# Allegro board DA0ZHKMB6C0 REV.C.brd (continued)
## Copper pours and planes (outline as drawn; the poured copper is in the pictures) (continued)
VDD10 on BOTTOM (solid shape): 150.84,70.38 150.84,68.81 148.6,66.57 146.93,66.57 146.91,66.57 146.65,66.47 146.55,66.21 146.55,66.19 145.66,65.3 145.28,65.3 145.05,65.53 145.05,65.53 144.64,65.94 144.49,65.94 143.86,66.57 143.64,66.57 143.63,66.58 143.12,66.58 143.11,66.57 142.84,66.57 142.21,65.94 142.21,60.6 142.08,60.48 141.06,60.48 140.94,60.6 140.94,67.21 142.08,68.35 143.58,68.35 143.68,68.25 143.68,68.25 143.72,68.22 144.05,68.22 144.26,68 144.26,67.71 144.33,67.21 144.83,67.27 145.08,67.27 145.13,67.23 145.2,67.21 145.21,67.21 145.22,67.19 145.53,67.19 145.54,67.2 145.56,67.21 145.68,67.27 145.73,67.4 145.74,67.41 145.74,67.7 145.73,67.72 145.67,67.83 145.56,67.89 145.54,67.89 145.53,67.9 145.52,67.9 145.24,68.18 145.22,68.29 145.32,68.35 147.01,68.35 147.07,68.34 147.11,68.29 147.11,68.1 147.17,68.03 147.22,67.97 147.28,67.93 147.34,67.86 147.61,67.86 147.69,67.94 147.72,67.97 147.75,68.01 147.81,68.06 147.88,68.07 147.94,68.02 148.51,67.95 148.41,68.52 148.36,68.59 148.39,68.68 148.57,68.86 148.57,69.76 149.32,70.51 150.71,70.51
VDD10 on IN2 (solid shape): outline of 94 points within 149.04,62.64 151.73,70.38
VDDREG/VDD33 on TOP (solid shape): 149.88,65.35 149.88,63.99 149.46,63.95 149.33,63.55 149.31,63.46 149.23,63.42 147.62,63.42 147.57,63.47 147.57,63.55 147.62,63.6 148.63,63.6 148.84,63.81 148.84,64.74 149.5,65.41 149.83,65.41
VDDREG/VDD33 on BOTTOM (solid shape): 150.59,67.34 150.59,64.54 150.46,64.41 149.85,64.41 149.72,64.29 149.44,64.29 148.78,64.95 147.51,64.95 147.41,65.05 147.41,66.1 147.52,66.21 148.78,66.21 150.08,67.51 150.41,67.51
554EN_1.0V on TOP (solid shape): 33.11,54.38 33.11,53.59 33.04,53.52 32.4,53.52 32.12,53.24 31.37,53.24 31.3,53.31 31.3,53.88 31.4,53.98 31.75,53.98 32.26,54.48 32.32,54.49 33,54.49
554EN_1.0V on BOTTOM (solid shape): 31.59,53.81 31.65,53.75 32.22,53.75 32.28,53.69 32.28,53.36 32.15,53.23 31.22,53.23 30.95,53.49 30.95,54.25 31.08,54.38 31.59,54.38
554LX_1.0V on TOP (solid shape): 27.93,53.98 27.93,53.96 28.24,53.8 28.54,53.96 28.55,53.98 28.59,54 29.6,54 29.6,53.41 29.8,53.41 29.8,54 30.11,54 30.11,53.43 30.3,53.43 30.3,54 30.57,54 30.6,53.97 30.6,53.37 30.56,53.36 30.25,52.94 30.64,52.6 30.96,52.6 31.08,52.48 31.08,51.33 31.84,50.57 31.84,45.24 31.72,45.11 29.24,45.11 29.16,45.14 29.14,45.22 29.04,45.51 28.76,45.62 28.54,45.52 28.43,45.31 28.43,45.29 28.41,45.27 28.35,45.27 28.29,45.33 28.29,46.69 27.78,47.19 27.35,47.19 26.76,47.78 26.76,53.52 27.25,54 27.88,54
554LX_1.8V on TOP (solid shape): 111.34,52.93 112.5,52.93 112.5,52.36 112.7,52.36 112.7,52.93 113,52.93 113,52.35 113.2,52.35 113.2,52.93 113.43,52.93 113.5,52.86 113.5,52.22 114.52,51.21 114.52,45.87 111.89,43.24 110.64,43.24 110.46,43.43 110.46,52.98 110.58,53.11 111.17,53.11
8690AGND on TOP (solid shape): 138.14,20.85 138.14,18.95 138.27,18.82 138.27,17.61 138.21,17.55 138.14,17.55 138.08,17.61 138.08,18.7 137.89,18.9 136.62,18.9 136.59,18.92 136.59,20.63 136.42,20.8 135.35,20.8 135.27,20.87 135.27,20.93 135.32,20.98 138.01,20.98
8690AGND on BOTTOM (solid shape): outline of 283 points within 132.93,13.87 140.94,22.5
51216DRVH on TOP (solid shape): 32.73,33.45 32.93,33.25 33.32,33.25 33.47,33.1 33.47,32.72 33.32,32.56 33.04,32.56 33.02,32.55 32.53,33.05 32.53,34.26 32.73,34.26
51216DRVH on TOP (solid shape): 36.61,27.31 36.61,26.9 36.92,26.59 36.92,25.99 36.86,25.93 35.75,25.93 35.65,26.02 35.65,27.33 35.78,27.46 36.46,27.46
51216DRVL on TOP (solid shape): 29.56,30.05 29.56,29.41 29.46,29.31 28.29,29.31 28.19,29.42 28.19,29.98 28.31,30.1 29.51,30.1
51216SW on TOP (solid shape): 32.33,33.05 33.06,32.31 33.24,32.31 33.27,32.28 33.27,31.8 33.24,31.78 32.58,31.78 32.12,32.23 32.12,34.26 32.33,34.26
51216SW on TOP (solid shape): 32.68,28.45 32.68,28.02 33.54,27.16 35.32,27.16 35.44,27.03 35.44,23.54 35.22,23.32 31.72,23.32 31.7,23.33 30.56,23.33 30.56,23.33 28.65,23.33 28.54,23.44 28.54,28.55 28.76,28.77 32.36,28.77
95833_LGATEG on BOTTOM (solid shape): 125.16,66.42 126.13,66.42 126.15,66.4 126.15,66.27 126.13,66.24 125.11,66.24 124.78,65.91 124.58,65.91 124.5,65.99 124.5,66.5 124.58,66.57 125.01,66.57
95833_PHASE1 on TOP (solid shape): 113.71,72.97 113.71,72.21 114.16,71.76 118.28,71.76 118.28,69.6 110.83,69.6 110.76,69.66 110.76,71.07 110.84,71.15 112.03,71.15 112.09,71.22 112.09,71.63 112.02,71.71 110.84,71.71 110.76,71.79 110.76,73.44 110.85,73.53 113.15,73.53
95833_PHASE1 on BOTTOM (solid shape): 126.13,64.39 126.13,64.26 126.1,64.24 125.31,64.24 125.06,63.98 124.63,63.98 123.94,63.3 123.13,63.3 123.1,63.32 123.1,64.03 123.33,64.26 124.04,64.26 124.06,64.27 124.29,64.27 124.43,64.41 124.5,64.41 124.63,64.29 124.96,64.29 125.1,64.43 126.08,64.43
95833_PHASEG on TOP (solid shape): 113.71,79.96 118.12,79.96 118.3,79.77 118.3,77.96 118.15,77.81 114.37,77.81 113.36,76.79 110.91,76.79 110.76,76.94 110.76,78.2 110.82,78.26 112.07,78.26 112.12,78.31 112.12,78.74 112.04,78.82 110.82,78.82 110.76,78.88 110.76,80.28 110.92,80.44 113.22,80.44
95833_PHASEG on BOTTOM (solid shape): 125.26,66.93 126.03,66.93 126.13,66.83 126.13,66.68 126.1,66.65 125.21,66.65 125.04,66.83 124.42,66.83 124.17,66.57 123.02,66.57 122.98,66.61 122.98,67.56 123,67.59 124.6,67.59
95833_UGATE1 on TOP (solid shape): 114.34,67.64 114.64,67.64 114.72,67.55 114.72,67.09 114.63,67.01 113.75,67.01 113.12,67.63 113.12,67.84 113.38,68.1 113.88,68.1
95833_UGATE1 on BOTTOM (solid shape): 126.1,63.98 126.1,63.63 126.05,63.58 125.92,63.58 125.56,63.21 125.12,63.21 125.11,63.2 124.71,63.2 124.63,63.27 124.63,63.63 124.78,63.78 125.16,63.78 125.39,64.01 126.08,64.01
+BATCHG on TOP (solid shape): outline of 3063 points within 59.27,2.87 119.85,27.05
+BATCHG on BOTTOM (solid shape): 63.8,15.9 63.88,15.86 63.94,15.44 64.23,15.29 64.85,15.29 64.99,15.29 65.14,15.35 65.2,15.5 65.21,15.65 65.23,15.87 65.3,15.9 65.88,15.9 65.94,15.84 65.94,15.74 65.93,15.65 65.94,15.55 65.94,12.44 65.9,12.36 65.8,12.35 65.32,12.01 65.8,11.68 65.9,11.67 65.94,11.59 65.94,10.79 65.59,10.44 61.64,10.44 61.33,10.74 61.33,14.76 61.71,15.14 62.04,15.14 62.22,15.09 62.41,15.14 62.98,15.14 63.21,15.37 63.21,15.75 63.36,15.9
+LCDVCC on TOP (solid shape): 31.52,67.96 31.52,64.82 31.37,64.67 28.03,64.67 27.91,64.8 27.91,67.93 28.08,68.1 31.38,68.1
+LCDVCC on BOTTOM (solid shape): 28.86,62.36 28.86,62.12 28.63,61.9 28.63,61.3 28.51,61.17 27.42,61.17 27.29,61.31 27.29,62.35 27.47,62.54 28.68,62.54
+LCDVCC on BOTTOM (solid shape): 31.73,67.87 31.73,66.39 31.74,66.38 31.95,66.38 31.96,66.39 31.96,67.88 32,67.92 32.19,67.92 32.24,67.87 32.24,66.39 32.24,66.38 32.45,66.38 32.46,66.39 32.46,67.87 32.51,67.92 32.68,67.92 32.73,67.87 32.73,65.42 32.61,65.3 32.61,64.88 32.51,64.77 30.35,64.77 29.68,65.44 29.68,66.07 29.81,66.19 31.33,66.19 31.46,66.32 31.46,67.87 31.51,67.92 31.68,67.92
+LCDVCC on IN1 (solid shape): 31.55,65.88 31.55,65.21 30.04,63.7 30.04,61.98 29.9,61.84 29.49,61.84 29.47,61.87 29.44,61.91 29.4,61.95 29.36,61.98 29.31,62 29.26,62.02 29.2,62.03 29.15,62.03 29.1,62.02 29.04,62 28.99,61.98 28.95,61.95 28.91,61.91 28.88,61.87 28.86,61.84 27.48,61.84 27.33,61.99 27.33,63.53 28.69,63.53 28.69,63.5 28.7,63.45 28.72,63.4 28.74,63.35 28.77,63.3 28.81,63.26 28.85,63.23 28.89,63.2 28.94,63.18 29,63.17 29.05,63.17 29.1,63.17 29.15,63.18 29.2,63.2 29.25,63.23 29.29,63.26 29.33,63.3 29.36,63.35 29.38,63.4 29.4,63.45 29.4,63.5 29.4,63.55 29.4,63.61 29.38,63.66 29.36,63.7 29.33,63.75 29.29,63.79 29.25,63.82 29.2,63.85 29.15,63.87 29.1,63.88 29.05,63.88 29,63.88 28.94,63.87 28.89,63.85 28.85,63.82 28.81,63.79 28.77,63.75 28.74,63.7 28.72,63.66 28.7,63.61 28.69,63.55 28.69,63.53 27.33,63.53 27.33,64.3 29.18,66.15 31.28,66.15
+TPVDD on BOTTOM (solid shape): 58.53,17.83 58.53,16.71 58.17,16.35 57.6,16.35 57.24,16.71 57.24,17.81 57.34,17.91 58.44,17.91
+TPVDD_1 on BOTTOM (solid shape): 59.74,20.51 59.74,19.06 59.63,18.95 59.02,18.95 58.82,19.15 58.82,20.6 58.4,21.02 57.08,21.02 56.66,20.6 56.66,16.46 56.35,16.15 56.35,15.37 56,15.01 51.52,15.01 51.4,15.13 51.4,16.41 51.53,16.54 52.92,16.54 53.97,17.58 54,17.58 54.08,17.54 54.1,17.46 54.53,17.07 54.77,17.59 54.76,17.61 54.77,17.64 54.86,17.73 54.86,19.28 54.17,19.96 52.34,19.96 52.24,20.07 52.24,20.85 52.32,20.93 55.57,20.93 56.46,21.82 58.44,21.82
+VA on TOP (solid shape): 154.33,88.19 154.33,82.68 154.23,82.58 150.8,82.58 150.67,82.7 150.67,88.18 150.91,88.42 154.1,88.42
+VA on BOTTOM (solid shape): 153.34,85.62 153.34,82.83 153.09,82.58 152.2,82.58 151.82,82.19 151.82,81.81 151.56,81.56 150.8,81.56 150.67,81.69 150.67,85.37 151.18,85.88 153.09,85.88
+VA_IACM on TOP (solid shape): 147.67,22.5 157.16,22.5 157.2,22.47 157.2,22.41 157.18,22.4 156.99,22.07 157.15,21.72 157.19,21.64 157.15,21.56 157.01,21.12 157.37,20.83 157.41,20.81 157.42,20.78 157.42,19.13 157.17,18.87 155.52,18.87 154.91,18.26 154.91,14.23 154.75,14.07 148.43,14.07 148.3,14.2 148.3,15.01 146.9,16.41 146.9,20.6 145.38,22.12 143.14,22.12 143.09,22.17 143.09,23.39 143.22,23.52 146.65,23.52
+VA_IACM on BOTTOM (solid shape): 156.33,85.76 156.33,84.01 157.15,83.2 157.15,82.07 156.9,81.81 155.23,81.81 154.74,82.31 154.35,82.31 154.1,82.55 154.1,85.6 154.48,85.98 156.11,85.98
+VA_IACM on SVCC (solid shape): outline of 85 points within 142.21,12.7 157.14,84.99
+VAD on TOP (solid shape): 142.43,19.69 142.64,19.69 142.66,19.71 145.58,19.71 145.81,19.47 145.81,14.22 145.69,14.1 145.05,14.1 144.9,14.25 144.9,14.73 144.54,15.09 143.02,15.09 142.59,15.52 142.59,16.3 140.48,18.4 140.48,18.95 140.49,18.99 140.53,19 141.48,19 141.48,19.2 140.53,19.2 140.49,19.21 140.48,19.25 140.48,19.35 140.49,19.38 140.53,19.4 141.48,19.4 141.48,19.6 140.53,19.6 140.49,19.61 140.48,19.65 140.48,19.75 140.49,19.79 140.53,19.8 141.48,19.8 141.48,20 140.53,20 140.49,20.01 140.48,20.05 140.48,20.15 140.49,20.18 140.53,20.2 141.48,20.2 141.48,20.4 140.53,20.4 140.49,20.41 140.48,20.45 140.48,20.55 140.49,20.58 140.53,20.6 141.52,20.6
ADOGND on TOP (solid shape): 22.02,83.69 22.02,82.94 22.32,82.65 22.32,81.04 22.23,80.96 21.05,80.96 21.02,80.99 21.02,81.22 21.1,81.29 21.46,81.29 21.8,81.63 21.8,82.38 21.7,82.48 21.7,82.96 21.29,83.37 21.29,83.64 21.49,83.84 21.87,83.84
ADOGND on TOP (solid shape): 21.81,85.53 21.81,84.63 21.66,84.47 19.4,84.47 19.4,84.48 13.28,84.48 13.23,84.51 13.23,84.53 13.01,84.83 12.66,84.95 11.94,84.95 11.63,84.86 11.41,84.62 11.41,84.61 11.15,84.35 5.96,84.35 5.4,84.91 2.96,84.91 2.87,84.88 2.78,84.84 2.56,84.67 2.47,84.4 2.47,82.59 2.44,82.54 2.42,82.54 1.63,81.49 2.43,80.46 2.45,80.46 2.47,80.43 2.47,79.73 3.28,78.92 3.3,78.8 3.2,78.75 3.16,78.75 2.44,78.75 1.85,78.15 2.44,77.55 3.16,77.55 3.64,77.8 3.72,78.34 3.71,78.37 3.77,78.43 3.8,78.4 4.05,78.4 4.25,78.25 4.49,78.2 5.21,78.2 5.45,78.25 5.65,78.4 8.09,78.4 8.65,77.84 8.65,75.01 8.65,73.61 9.31,72.95 9.31,66.25 10.39,65.16 13.55,65.16 13.62,65.08 13.62,64.81 12,63.19 3.26,63.19 2.2,66 0.61,68.55 0.53,68.69 0.51,68.84 0.51,75.8 0.57,76.04 1.27,76.76 1.46,77.5 1.46,78.45 1.46,84.4 1.46,84.42 1.46,85.12 14.92,85.12 15.29,85.49 20.6,85.49 21.02,85.53 21.44,85.64 21.71,85.64
ADOGND on BOTTOM (solid shape): outline of 93 points within 0.51,63.19 21.81,85.64
ADOGND on SGND (solid shape): outline of 306 points within 0.51,63.2 33.42,85.63
ADOGND on IN1 (solid shape): 21.81,85.53 21.81,84.63 21.66,84.47 19.4,84.47 19.4,84.48 13.28,84.48 13.23,84.51 13.23,84.53 13.01,84.83 12.66,84.95 11.94,84.95 11.67,84.88 11.46,84.7 11.43,84.66 11.41,84.61 11.15,84.35 5.96,84.35 5.4,84.91 2.96,84.91 2.87,84.88 2.78,84.84 2.56,84.67 2.47,84.4 2.47,82.59 2.44,82.54 2.42,82.54 1.63,81.49 2.43,80.46 2.47,80.43 2.47,78.75 2.43,78.75 1.98,78.53 1.85,78.05 1.87,77.99 1.89,77.93 1.94,77.83 2.01,77.74 2.01,77.43 3.37,76.07 8.09,76.07 9.64,74.52 9.64,73.37 9.31,73.03 9.31,66.25 10.39,65.16 13.55,65.16 13.62,65.08 13.62,64.81 12,63.19 3.26,63.19 2.2,66 0.61,68.55 0.53,68.69 0.51,68.84 0.51,75.8 0.57,76.04 1.27,76.76 1.46,77.5 1.46,78.45 1.46,84.4 1.46,84.42 1.46,85.27 1.46,85.38 1.48,85.5 13.01,85.5 13.11,85.49 13.2,85.49 20.6,85.49 21.02,85.53 21.44,85.64 21.71,85.64
ADOGND on IN2 (solid shape): outline of 81 points within 0.51,63.19 21.81,85.64
ADOGND on SVCC (solid shape): outline of 294 points within 0.76,63.2 33.42,85.5
CHG_LX on TOP (solid shape): 131.66,25.28 131.66,23.33 132.11,22.89 133.19,22.89 134.28,21.79 136.52,21.79 136.59,21.87 136.59,22.45 136.6,22.48 136.61,22.5 136.64,22.5 137.61,22.5 137.68,22.58 137.68,23.75 137.69,23.78 137.71,23.79 137.86,23.79 137.88,23.78 137.89,23.75 137.89,22.8 137.89,22.8 137.89,22.58 137.96,22.5 138.14,22.5 138.16,22.48 138.17,22.45 138.17,21.39 138.16,21.36 138.14,21.34 138.12,21.34 136.41,21.34 136.29,21.21 135.12,21.21 134.36,20.45 132.48,20.45 132.08,20.05 132.08,18.3 131.72,17.93 127.73,17.93 127.47,18.19 127.47,21.4 136.28,21.4 136.28,21.6 135.29,21.6 135.29,21.4 127.47,21.4 127.47,24.13 127.75,24.41 129.63,24.41 129.76,24.54 129.76,25.3 130.01,25.55 131.39,25.55
CHG_VBATT on TOP (solid shape): 142.18,24 142.37,24 142.42,23.98 142.47,23.98 142.69,23.76 142.69,23.75 142.71,23.73 142.71,22.25 142.26,21.79 142.26,21.06 142,20.8 140.48,20.8 140.48,21 141.48,21 141.48,21.2 140.48,21.2 140.48,21.4 141.48,21.4 141.48,21.6 140.48,21.6 140.48,21.8 141.48,21.8 141.48,22 140.48,22 140.48,22.2 141.48,22.2 141.48,22.4 140.48,22.4 140.48,23.72 140.78,24.03 142.15,24.03
CHG_VBATT on TOP (solid shape): 126.58,28.14 126.58,18.44 126.2,18.06 121.93,18.06 121.56,18.44 121.56,20.56 121.57,20.59 121.59,20.61 121.89,20.98 121.59,21.35 121.57,21.37 121.56,21.4 121.56,22.83 120.74,23.65 120.74,26.82 120.97,27.05 124.36,27.05 125.54,28.23 126.5,28.23
CHG_VBATT on IN1 (solid shape): outline of 348 points within 123.03,22.38 143.68,26.92
CODEC_VREF on TOP (solid shape): 17.26,75.84 18.14,75.84 18.23,75.76 18.34,75.76 18.43,75.67 19.47,75.67 19.47,75.67 19.47,75.49 19.46,75.48 18.44,75.48 18.43,75.46 17.09,75.46 16.91,75.29 16.55,75.29 16.45,75.39 16.45,75.82 16.53,75.9 17.21,75.9
CORE_V1P05_S3_PW on TOP (solid shape): 70.74,57.96 71,58.09 71.16,58.09 72.05,57.2 72.26,57.2 72.3,57.2 72.43,57.2 72.93,57.71 73.09,57.71 73.47,57.46 73.85,57.71 73.95,57.71 74.08,57.58 74.08,56.69 73.95,56.57 73.77,56.57 73.73,56.58 73.61,56.67 73.45,56.7 73.43,56.71 73.39,56.75 73.37,56.8 73.33,56.84 73.28,56.9 73.25,56.92 73.17,57 72.89,57 72.83,56.94 72.49,56.94 72.3,57 72.12,56.94 72.03,56.94 71.92,56.82 71.79,56.82 70.9,57.71 70.85,57.71 70.84,57.71 70.74,57.73 70.64,57.71 70.63,57.71 70.06,57.71 70.05,57.71 69.83,57.7 69.69,57.53 69.69,57.51 69.38,57.2 69.12,57.2 68.97,57.05 68.96,57.05 68.47,56.57 68.24,56.57 68.17,56.64 68.15,56.67 68.13,56.7 68.13,57.61 68.29,57.76 69.3,57.76 69.54,58 69.81,58 69.82,57.99 70.01,57.96 70.17,58.07 70.21,58.09 70.48,58.09
CORE_V1P05_S3_PW on BOTTOM (solid shape): 60.9,54.61 60.9,53.62 60.7,53.42 60.29,53.42 60.14,53.57 60.14,53.95 60.01,54.08 60.01,54.64 60.06,54.69 60.82,54.69
CORE_V1P05_S3_PW on BOTTOM (solid shape): 71.52,57.71 71.57,57.71 71.59,57.7 71.6,57.68 71.91,57.49 72.23,57.68 72.24,57.7 72.26,57.71 73.06,57.71 73.44,57.33 73.54,57.33 73.7,57.18 73.7,56.97 73.54,56.82 70.77,56.82 70.7,56.85 70.67,56.91 70.34,57.5 70.02,56.91 69.99,56.85 69.92,56.82 68.57,56.82 68.49,56.74 67.96,56.74 67.86,56.85 67.86,57.23 67.96,57.33 68.6,57.33 68.6,57.33 69.51,57.33 69.51,57.33 69.59,57.33 69.97,57.71 70.1,57.71 70.25,57.86 71.37,57.86
CORE_V1P05_S3_PW on IN1 (solid shape): 71.56,58.04 71.58,58.02 71.57,57.99 71.73,57.57 72.18,57.64 72.19,57.65 72.21,57.66 73.15,57.66 73.17,57.65 73.19,57.64 73.43,57.51 73.69,57.58 73.72,57.59 73.76,57.58 73.88,57.46 73.88,56.77 73.75,56.64 73.59,56.64 73.53,56.66 73.46,56.67 72.87,56.67 72.85,56.64 72.02,56.64 72.01,56.64 71.91,56.66 71.81,56.64 71.81,56.64 71.14,56.64 71.1,56.68 71.09,56.67 70.69,56.67 70.6,56.73 70.61,56.84 70.35,57.43 70.08,56.84 70.1,56.73 70.01,56.67 69.69,56.67 69.59,56.57 69.01,56.57 68.78,56.66 68.55,56.58 68.54,56.57 68.42,56.57 68.34,56.64 68.34,58.15 68.44,58.24 71.37,58.24
CORE_V1P05_S3_PW on IN2 (solid shape): outline of 205 points within 60.25,53.26 69.36,57.54
DARM_V1P0_SOIX_PWR on TOP (solid shape): 66.89,56.93 67.01,56.79 67.16,56.73 67.18,56.73 67.47,56.44 68.49,56.44 68.57,56.52 68.78,56.73 68.8,56.73 68.97,56.79 69.1,56.93 69.12,56.95 69.97,56.95 70.25,56.67 70.42,56.67 70.49,56.6 70.5,56.59 70.55,56.52 70.62,56.47 70.65,56.44 71.79,56.44 72.11,56.76 72.18,56.82 72.2,56.82 72.43,56.82 72.55,56.69 72.55,55.93 72.43,55.81 71.54,55.81 71.16,56.19 70.86,56.19 70.85,56.19 70.66,56.21 70.51,56.08 70.5,56.07 70.48,56.06 70.27,56.06 70.14,56.19 70.08,56.19 70.07,56.19 69.83,56.19 69.69,56 69.69,55.99 69.38,55.68 69.12,55.68 68.62,56.19 68.51,56.19 68.5,56.19 68.38,56.22 68.27,56.19 68.26,56.19 68.24,56.19 67.85,55.81 66.71,55.81 66.58,55.93 66.58,56.82 66.71,56.95 66.86,56.95
DARM_V1P0_SOIX_PWR on BOTTOM (solid shape): outline of 416 points within 48.1,53.35 72.17,57.08
DDI_V1P0_SOIX on BOTTOM (solid shape): 49.19,57 49.19,56.85 49.29,56.74 51.78,56.74 51.88,56.64 51.88,55.96 51.83,55.9 51.29,55.9 50.82,56.06 50.64,55.59 50.64,55.49 50.55,55.45 50.4,55.3 48.94,55.3 48.76,55.47 48.17,55.47 48.12,55.52 48.12,56.08 48.66,56.62 48.66,57.05 48.76,57.15 49.04,57.15
DDI_V1P0_SOIX on IN2 (solid shape): 67.6,65.46 67.6,65.37 67.6,63.97 67.6,63.91 67.6,63.86 67.6,63.3 67.52,63.22 67.1,63.22 66.84,63.48 66.84,64.5 66.85,64.51 66.85,64.88 66.84,64.89 66.84,65.08 66.71,65.2 66.38,65.2 66.23,65.35 66.23,65.62 66.33,65.71 67.35,65.71
HWPG1.8VD on BOTTOM (solid shape): 119.09,59.59 119.09,59.21 118.84,58.95 117.95,58.95 117.82,59.08 117.82,60.3 117.84,60.34 117.87,60.35 118.33,60.35
L_SPK+ on TOP (solid shape): 21.91,71.91 21.95,71.89 21.97,71.86 21.97,70.56 21.79,70.38 21.79,69.42 21.78,69.42 21.78,69.04 21.78,68.63 21.71,68.55 21.43,68.55 21.31,68.67 21.31,69.86 21.44,69.99 21.44,70.32 21.76,70.64 21.76,71.91 21.76,71.91
L_SPK+ on IN1 (solid shape): 21.78,69.98 21.78,67.97 21.71,67.89 21.12,67.89 21.03,67.99 21.01,68.01 21.01,68.04 21.02,68.14 21,68.25 21,68.26 21,68.73 21.3,69.04 21.3,69.77 21.35,69.82 21.35,70.03 21.4,70.08 21.68,70.08
L_SPK+_1 on TOP (solid shape): 10.63,9.3 10.63,6.88 10.38,6.63 9.01,6.63 8.86,6.78 8.86,9.3 9.11,9.55 10.38,9.55
L_SPK+_1 on BOTTOM (solid shape): 13.17,12.24 13.17,9.42 12.49,8.74 9.47,8.74 9.26,8.53 9.11,8.53 8.98,8.66 8.98,9.63 9.16,9.8 9.36,9.8 9.62,10.06 11.01,10.06 12.03,11.07 12.03,11.99 12.36,12.32 13.1,12.32
L_SPK- on TOP (solid shape): 22.31,71.91 22.35,71.89 22.37,71.86 22.37,70.61 22.44,70.53 22.44,69.04 22.34,68.94 22.04,68.94 21.94,69.04 21.94,70.38 22.16,70.61 22.16,71.91
L_SPK- on IN1 (solid shape): 22.5,69.98 22.5,69.93 22.49,69.93 22.47,69.8 22.49,69.67 22.5,69.67 22.5,69.32 22.49,69.32 22.54,68.98 22.84,68.83 22.85,68.83 23.16,68.53 23.16,68.25 22.98,68.07 22.4,68.07 21.89,68.59 21.89,69.95 22.01,70.08 22.39,70.08
L_SPK-_1 on TOP (solid shape): 12.67,9.38 12.67,6.76 12.54,6.63 11.4,6.63 11.39,6.64 11.27,6.64 11.14,6.77 11.14,9.3 11.4,9.55 12.49,9.55
L_SPK-_1 on BOTTOM (solid shape): 14.44,12.22 14.44,8.79 13.43,7.77 13.43,6.76 13.17,6.5 12.16,6.5 12.03,6.63 12.03,7.77 13.55,9.3 13.55,12.27 13.58,12.29 14.37,12.29
LAN_MCT0 on TOP (solid shape): 141.07,84.59 141.07,84.32 140.82,84.06 140.82,84 140.82,82.76 140.05,82.76 140.05,84.67 140.07,84.7 140.96,84.7
LAN_MCT1 on TOP (solid shape): 139.54,84.96 139.54,82.78 138.78,82.78 138.78,84.15 138.15,84.78 137.73,84.78 137.65,84.86 137.65,85.29 137.85,85.5 139,85.5
LAN_MCT2 on TOP (solid shape): 133.67,84.77 133.67,84.31 133.43,84.07 133.24,84.07 133.18,84 133.18,82.77 132.42,82.77 132.42,84.04 132.43,84.05 132.43,85.01 132.64,85.22 133.22,85.22
LAN_MCT2 on BOTTOM (solid shape): 134.42,85.05 134.48,85.01 134.55,84.96 134.55,83.08 134.45,82.98 133.09,82.98 133.03,83.04 133.03,85.02 133.08,85.05
LAN_MCT3 on TOP (solid shape): 131.92,84.82 131.92,82.96 131.92,82.77 131.17,82.77 131.17,84.21 130.65,84.73 130.65,85.12 130.78,85.24 131.5,85.24
LANCT3 on TOP (solid shape): 147.29,80.84 147.29,77.99 147.08,77.78 144.92,77.78 144.75,77.95 144.75,80.85 144.82,80.92 147.2,80.92
LANCT3 on BOTTOM (solid shape): 145.46,83.06 145.46,81.52 145.89,81.09 147.21,81.09 147.26,81.04 147.26,80.1 147.14,79.97 139.01,79.97 138.08,80.9 129.81,80.9 129.4,81.32 129.4,82.02 129.6,82.22 138.89,82.22 139.44,81.67 143.07,81.67 143.78,82.38 143.78,83.29 143.88,83.39 145.13,83.39
LANVCC on TOP (solid shape): 144.69,65.23 144.69,64.14 144.67,64.11 144.54,64.11 143.86,64.8 143.86,65.43 143.98,65.56 144.36,65.56
LANVCC on BOTTOM (solid shape): outline of 171 points within 142.43,57.28 149.06,65.74
LANVCC on IN2 (solid shape): 145.53,57.81 146.29,57.81 146.63,57.48 146.63,57.35 146.5,57.23 145.48,57.23 144.21,58.5 144.04,58.5 143.93,58.54 143.81,58.54 143.8,58.54 143.78,58.55 143.58,58.75 143.58,59 143.83,59.26 144.08,59.26
LGND on TOP (solid shape): 147.16,84.75 147.16,82.45 144.87,82.45 144.75,82.58 144.75,85.37 144.87,85.5 146.41,85.5
LGND on BOTTOM (solid shape): outline of 106 points within 124.04,83.64 146.93,101.19
MIC2_MIC_RING2_MIC on TOP (solid shape): 29.94,81.99 32,81.99 32.07,81.92 32.07,80.54 32,80.47 30.6,80.47 29.84,79.71 28.97,79.71 28.87,79.81 28.87,81.91 29.09,82.13 29.8,82.13
MIC2_MIC_RING2_MIC on IN1 (solid shape): outline of 445 points within 3.12,80.8 32.07,84.71
MIC2_MIC_SLEEVE_MIC on TOP (solid shape): 10.1,76.51 10.1,75.13 9.87,74.9 9.06,74.9 8.88,75.08 8.88,76.53 9.03,76.68 9.92,76.68
MIC2_MIC_SLEEVE_MIC on TOP (solid shape): 12.69,74.36 12.69,73.15 12.59,73.05 10.75,73.05 10.54,73.26 10.54,73.42 10.56,73.43 10.56,73.97 11.03,74.44 12.61,74.44
MIC2_MIC_SLEEVE_MIC on IN1 (solid shape): outline of 144 points within 2.15,73.01 11.62,80.01
NB670SW on TOP (solid shape): 120.06,46.46 120.06,45.21 121.17,44.1 121.17,43.9 121.39,43.69 122.7,43.69 122.85,43.54 122.85,42.37 123.16,42.06 123.54,42.06 123.65,41.95 123.65,41.44 123.03,40.82 122.29,40.82 122.28,40.83 117.79,40.83 116.42,42.19 116.42,43.84 116.94,44.36 119.49,44.36 119.49,45.45 119,45.45 119,44.36 116.94,44.36 117.06,44.48 117.92,44.48 118.69,45.24 118.69,46.48 118.69,46.49 119.09,46.49 119.09,45.83 119.09,45.83 119.09,45.8 119.47,45.8 119.47,45.83 119.48,45.83 119.48,46.49 119.47,46.49 119.47,46.51 119.09,46.51 118.69,46.49 118.84,46.63 119.88,46.63
NB671SW on TOP (solid shape): 153.84,39.06 153.84,33.4 153.74,33.3 152.49,33.3 152.39,33.4 152.39,33.42 153.31,33.42 153.31,34.08 152.91,34.08 152.91,33.42 152.39,33.42 152.39,34.46 153.4,34.46 153.4,35.55 152.9,35.55 152.9,34.46 152.39,34.46 152.39,35.12 152.3,35.2 149.19,35.2 149.06,35.33 149.06,36.04 149.11,36.09 149.52,36.09 149.6,36.17 149.6,39.04 149.88,39.31 153.59,39.31
R_SPK+ on TOP (solid shape): 23.17,71.91 23.17,70.93 23.25,70.85 23.26,70.83 23.26,70.8 23.88,70.18 23.88,69.67 23.78,69.56 23.78,69.12 23.78,68.65 23.67,68.55 23.4,68.55 23.21,68.75 23.21,69.49 23.21,70.51 22.96,70.76 22.96,71.91 22.96,71.91 23.16,71.91
R_SPK+ on BOTTOM (solid shape): 23.84,69.88 23.84,69.45 23.84,69.44 23.77,69.09 23.84,68.73 23.84,68.72 23.84,68.61 24.07,68.36 24.22,68.22 24.22,67.59 24.13,67.5 23.55,67.5 23.21,67.84 23.21,69.88 23.33,70 23.71,70
R_SPK+_1 on TOP (solid shape): 16.6,9.27 16.6,6.76 16.48,6.63 14.53,6.63 14.44,6.71 14.44,9.3 14.57,9.42 16.45,9.42
R_SPK+_1 on BOTTOM (solid shape): 17.24,11.96 17.24,6.75 16.99,6.5 16.22,6.5 15.97,6.76 15.97,12.09 16.09,12.22 16.98,12.22
R_SPK- on TOP (solid shape): 22.77,71.91 22.77,70.67 23.1,70.33 23.1,69.45 23.11,69.01 23,68.91 22.67,68.91 22.56,69.02 22.56,71.91 22.56,71.91 22.76,71.91
R_SPK- on BOTTOM (solid shape): 23.08,69.88 23.08,67.72 22.83,67.46 22.32,67.46 22.19,67.59 22.19,68.73 22.31,68.86 22.32,68.86 22.44,68.94 22.52,69.06 22.53,69.07 22.57,69.11 22.57,69.88 22.7,70 22.95,70
R_SPK-_1 on TOP (solid shape): 14.19,9.3 14.19,6.88 13.94,6.63 13.05,6.63 12.92,6.76 12.92,9.42 13.05,9.55 13.94,9.55
R_SPK-_1 on BOTTOM (solid shape): 15.71,12.22 15.71,6.83 15.51,6.63 13.81,6.63 13.68,6.76 13.68,7.77 14.7,8.79 14.7,12.19 14.85,12.34 15.59,12.34
REGOUT on TOP (solid shape): 152.44,68.51 152.44,67.49 152.01,67.06 150.48,65.53 149.76,65.53 149.75,65.54 149.62,65.56 149.49,65.54 149.48,65.53 149.44,65.53 149.35,65.45 149.31,65.4 148.7,64.78 148.7,63.97 148.56,63.83 147.72,63.83 147.62,63.93 147.62,64.06 147.65,64.09 147.65,64.95 149.75,67.06 149.75,67.63 149.75,68.45 150.03,68.73 152.22,68.73
RING2 on TOP (solid shape): 23.26,79.29 23.26,78.66 22.95,78.35 22.89,78.35 22.77,78.23 22.76,77.23 22.7,77.17 22.62,77.17 22.58,77.21 22.58,78.24 22.56,78.25 22.56,79.19 22.56,79.25 22.56,79.25 22.56,79.4 22.66,79.5 23.06,79.5
RING2 on TOP (solid shape): 28.26,81.74 28.26,79.83 28.13,79.71 27.25,79.71 27.16,79.79 27.16,80.58 27.13,80.61 27.13,81.07 26.77,81.43 25.62,81.43 25.49,81.31 25.49,80.8 25.37,80.67 25.08,80.67 25.06,80.68 25.05,80.69 24.99,80.76 24.91,80.81 24.87,80.83 24.81,80.85 24.7,80.96 22.92,80.96 22.83,81.05 22.83,82.32 22.95,82.45 27.55,82.45
RING2 on BOTTOM (solid shape): 24.1,82.45 24.1,78.82 24.05,78.73 24.03,78.63 23.87,78.46 22.75,78.46 22.52,78.69 22.52,82.43 22.67,82.58 23.97,82.58
SLEEVE on TOP (solid shape): 12.69,72.71 12.69,71.5 12.59,71.4 10.75,71.4 10.54,71.6 10.54,71.77 10.56,71.78 10.56,72.32 11.03,72.79 12.61,72.79
SLEEVE on TOP (solid shape): 15.48,75.13 15.98,75.13 16.22,74.89 16.22,74.44 16.17,74.39 15.44,74.39 14.99,74.84 14.99,75.12 15.11,75.25 15.35,75.25
SLEEVE on TOP (solid shape): 20.31,79.99 20.97,79.99 21.04,79.92 21.04,79.92 22.31,79.92 22.36,79.87 22.36,77.16 22.32,77.11 22.24,77.11 22.16,77.19 22.16,78.26 22.03,78.39 22.03,79.07 21.74,79.36 20.55,79.36 20.26,79.51 19.97,79.36 19.67,79.36 19.63,79.4 19.63,79.58 19.07,80.14 19.07,80.39 19.19,80.52 19.78,80.52
SLEEVE on IN1 (solid shape): outline of 290 points within 10.45,71.31 21.18,81.67
TPM_VDD on TOP (solid shape): 45.79,51.61 45.79,51.11 46.78,50.11 46.78,48.05 47.83,47 47.83,46.04 48.58,45.29 50.64,45.29 51.37,44.56 51.37,43.75 50.89,43.28 50.89,42.52 51.55,41.86 51.55,40.51 51.1,40.06 51.1,36.45 50.96,36.31 44.66,36.31 44.03,36.94 41.76,36.94 41.7,37.01 41.7,37.36 41.79,37.45 44.14,37.45 44.24,37.43 44.32,37.38 44.88,36.82 46.03,36.82 46.14,36.93 46.14,38 45.76,38.38 45.43,38.38 45.33,38.47 45.33,38.74 45.46,38.86 46.48,38.86 46.65,38.69 46.65,36.96 46.79,36.82 49.78,36.82 50.21,37.25 50.21,40.89 50.29,40.98 50.59,40.98 50.88,41.27 50.88,41.75 50.33,42.29 50.33,43.44 50.86,43.96 50.86,44.35 50.43,44.78 48.37,44.78 47.32,45.83 47.32,46.79 46.26,47.85 45,47.85 44.97,47.88 44.97,48.29 45.12,48.43 45.88,48.43 46.07,48.62 46.07,49.84 45.76,50.14 45.46,50.14 45.22,50.37 45.22,51.16 44.96,51.43 44.58,51.43 44.18,51.03 44.18,51.03 43.77,50.61 43.77,50.49 43.72,50.43 42.99,50.43 42.94,50.48 42.94,51 43.25,51.31 43.25,51.69 43.55,51.99 45.41,51.99
UNCORE_V1P8_AN32_PWR on BOTTOM (solid shape): outline of 442 points within 73.19,54.92 81.5,57.05
UNCORE_V1P8_AN32_PWR on IN1 (solid shape): 73.56,55.88 73.6,55.87 73.61,55.83 73.61,55.32 73.52,55.22 73.52,54.93 73.35,54.76 72.91,54.76 72.88,54.77 72.86,54.79 72.55,54.97 72.24,54.79 72.22,54.77 72.2,54.76 71.88,54.76 71.86,54.77 71.84,54.79 71.47,54.95 71.18,54.66 71,54.66 70.92,54.58 70.89,54.57 70.86,54.58 70.65,54.68 70.43,54.71 70.35,54.74 70.32,54.81 70.32,55.14 70.38,55.2 70.4,55.2 70.51,55.23 70.6,55.3 70.64,55.34 72.55,55.34 73.09,55.88
USB3_V1P0_G3 on BOTTOM (solid shape): 81.06,73.33 81.06,71.75 80.72,71.41 80.07,71.41 79.95,71.53 79.95,71.93 79.79,72.55 79.29,72.14 79.13,71.98 79,71.92 78.9,71.82 78.69,71.82 78.47,72.03 78.47,73.31 78.62,73.46 80.94,73.46
V_BLIGHT on TOP (solid shape): 27.14,67.46 27.14,65.05 27.02,64.92 24.94,64.92 24.86,65.01 24.86,65.59 24.86,65.61 24.87,65.63 25.11,65.86 25.44,65.86 25.75,66.03 25.76,66.38 25.75,66.4 25.77,66.53 25.75,66.66 25.76,66.69 25.8,66.82 25.78,66.96 25.75,67.04 25.77,67.17 25.75,67.28 25.75,67.29 25.75,67.32 26.02,67.59 27.02,67.59
V_BLIGHT on BOTTOM (solid shape): outline of 116 points within 25.94,62.59 30.32,68.73
VIS_V1P0_SIOX_PW on BOTTOM (solid shape): outline of 104 points within 48.16,56.29 56.2,59.93
VIS_V1P0_SIOX_PW on IN1 (solid shape): 70.03,62.98 70.04,62.97 70.29,62.8 70.59,62.89 71.65,62.89 71.72,62.84 71.81,62.81 71.91,62.8 72.01,62.82 72.02,62.82 72.05,62.82 72.23,62.63 72.23,62.38 72.06,62.2 69.8,62.2 68.31,63.7 68.31,63.76 68.32,63.77 68.35,63.89 68.33,64.01 68.33,64.03 68.34,64.05 68.44,64.16 68.85,64.16
VIS_V1P0_SIOX_PW on IN2 (solid shape): outline of 391 points within 64.19,58.44 69.12,64.19
N18314354 on TOP (solid shape): 111.97,60.23 111.97,58.69 111.98,58.69 111.98,56.54 112.23,56.29 112.74,56.29 113,56.03 113,55.14 112.87,55.02 112.7,55.02 112.7,55.63 112.5,55.63 112.5,55.02 112.23,55.02 111.85,55.4 110.58,55.4 110.46,55.52 110.46,56.41 110.33,56.54 109.69,56.54 109.57,56.67 109.57,57.05 109.69,57.18 110.46,57.18 110.71,57.43 110.71,60.22 110.84,60.35 111.85,60.35
N18314480 on TOP (solid shape): 30.93,60.73 30.95,60.73 30.97,60.72 31.07,60.62 31.08,60.6 31.08,60.58 31.08,59.1 31.08,59.08 31.07,59.07 30.21,58.21 30.2,58.19 30.19,58.17 30.19,57.76 30.54,57.41 30.54,57.25 30.12,56.82 30.12,56.16 30.11,56.14 30.08,56.11 29.85,56.11 29.82,56.12 29.8,56.16 29.8,56.63 29.79,56.67 29.75,56.68 29.66,56.68 29.62,56.67 29.6,56.63 29.6,56.16 29.59,56.12 29.55,56.11 29.15,56.11 29.13,56.11 29.11,56.12 28.94,56.3 28.93,56.31 28.92,56.33 28.92,58.12 28.92,58.14 28.91,58.16 28.88,58.18 28.87,58.2 28.81,58.31 28.71,58.36 28.69,58.37 28.3,58.76 28.29,58.78 28.29,58.8 28.29,60.15 28.42,60.27 29.61,60.27 30.06,60.73
N19249672 on BOTTOM (solid shape): 49.47,19.86 49.47,18.61 49.23,18.37 47.38,18.37 47.31,18.44 47.31,18.66 49.27,18.66 49.27,19.82 48.97,19.82 48.97,18.66 47.31,18.66 47.31,19.89 47.43,20 49.33,20
N19870274 on TOP (solid shape): 140.81,73.5 140.62,73.3 139.03,73.3 138.76,73.57 138.76,75.29 140.81,75.29
N19870274 on TOP (solid shape): 133.17,74.06 133.44,73.79 133.44,73.69 133.19,73.43 132.17,73.43 132.17,73.44 132,73.44 131.86,73.58 131.86,73.73 131.53,74.05 131.42,74.05 131.16,74.32 131.16,75.29 133.17,75.29
N19870274 on BOTTOM (solid shape): 141.68,74.97 141.68,73.64 141.35,73.3 132.09,73.3 131.89,73.51 131.89,73.89 131.97,73.98 131.97,74.85 132.33,75.21 141.44,75.21
N20841552 on BOTTOM (solid shape): 7.37,92.44 9.69,90.1 9.69,89 9.83,88.01 10.25,87.1 10.25,86.39 10.06,86.2 6.48,86.2 6.16,85.88 5.45,85.88 5.07,86.26 3.48,86.26 3.25,86.49 3.25,87.05 4.52,88.37 5.01,90.14
N77164358 on BOTTOM (solid shape): 23.51,43.65 23.51,42.99 22.86,42.35 22.86,41.7 22.86,40.95 23.05,40.75 23.05,40.41 22.95,40.31 22.8,40.31 22.38,40.73 22.38,42.47 21.81,43.04 21.48,43.04 21.16,43.35 21.16,43.64 21.3,43.78 23.37,43.78

Small or netless copper shapes (teardrops, artwork), in the pictures only: 15 on TOP, 69 on BOTTOM, 1 on IN1, 16 on IN2

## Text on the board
Ref Des/Silkscreen Bottom: REV:C | DA0ZHKMB6BC
User.Comments: 24.0x55.0 | 43.0x55.0 | 24.0x59.0 | 24.0x79.0 | 28.0x91.0 | 43.0x91.0 | 35.0x94.0 | 39.0x279.0 | 39.0x475.0
Ref Des/Silkscreen Top: DA0ZHKMB6C0 | REV:A | MODEL:ZHK
User.12: GND | +5V_S5 | ADOGND | +VCC_GFX | +VCC_CORE | +VIN | +VA_IACM
User.21: 169.2 | 103
User.24: ADOGND | GND
User.45: FIGURE | TYPE | Oblong | SIZE | 24.0x16.0 | 51.0x24.0 | DRILL CHART: TOP to BOTTOM | ALL UNITS ARE IN MILS | PLATED | NON-PLATED | ROTATION | 0.000 | 90.000 | QTY | 26 | 8 | 2 | 4 | 1 | 58 | Circle | 10.0 | 12.0 | 14.0 | 22.0 | 24.0 | 28.0 | 32.0 | 35.0 | 36.0 | 59.0 | 83.0 | 106.0 | 110.0 | 118.0 | 140.0 | 335.0 | 43.0 | 44.0 | 47.0 | 51.0 | 55.0 | 63.0 | 67.0 | 70.0 | - | 2495 | 14 | 577 | 19 | 60 | 22 | 9 | 7 | 3 | 3242 | TOTAL HOLES:
